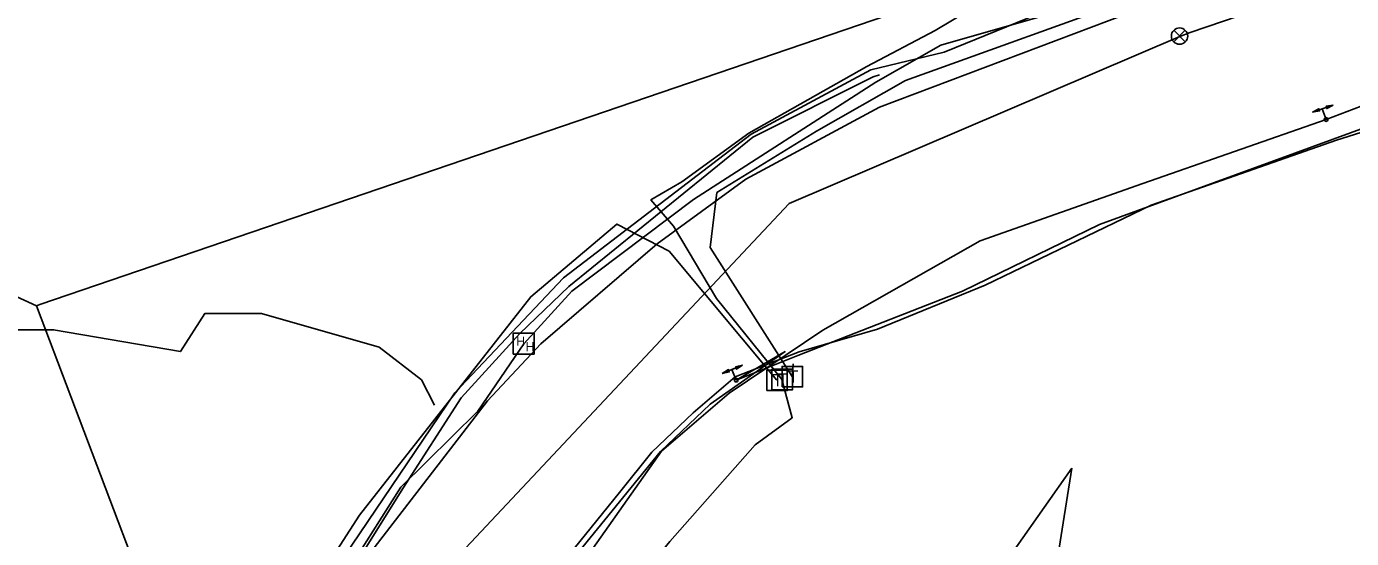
# Model space of a CAD drawing. Extents: x 2070721 to 2083340, y 729290 to 737883.
# Drawn here: x 2080183.4 to 2080544.7, y 734411.8 to 734551.5 of the extents above; entities that cross this region are included whole.
import ezdxf

# ---------------------------------------------------------------- set-up
doc = ezdxf.new("R2010")
doc.units = 0
for name, color, linetype in [('Exist Utilities Other Unknown UG SUE LOS B', 7, 'Continuous'), ('Exist Utilities Power Change of Service SUE CELL', 7, 'Continuous'), ('Exist Utilities Power UG Cable SUE LOS B', 7, 'Continuous'), ('Exist Utilities Power UG Cable SUE LOS C', 7, 'Continuous'), ('Exist Utilities Telephone Hand Hole CELL', 7, 'Continuous'), ('Exist Utilities Telephone Pedestal CELL', 7, 'Continuous'), ('Exist Utilities Telephone UG Cable SUE LOS C', 7, 'Continuous'), ('Exist Utilities Telephone UG Conduit SUE LOS B', 7, 'Continuous'), ('Exist Utilities Telephone UG FO SUE LOS B', 7, 'Continuous'), ('Exist Utilities TV Change of Service SUE CELL', 7, 'Continuous'), ('Exist Utilities TV UG Cable SUE LOS B', 7, 'Continuous'), ('Exist Utilities TV UG FO Cable SUE LOS B', 7, 'Continuous'), ('Exist Utilities TV UG FO Cable SUE LOS C', 7, 'Continuous'), ('Exist Utilities Water UG Line SUE LOS B', 7, 'Continuous'), ('Exist Utilities Water Valve CELL', 7, 'Continuous')]:
    doc.layers.add(name, color=color, linetype=linetype)

msp = doc.modelspace()

# ---------------------------------------------------------------- linework, layer by layer
at = {"layer": 'Exist Utilities Other Unknown UG SUE LOS B'}
msp.add_lwpolyline([(2080237.92, 734293.08), (2080243.61, 734324.09), (2080258.34, 734369.36), (2080269.39, 734398.77), (2080286.02, 734425.45), (2080301.91, 734450.14), (2080317.89, 734467.75), (2080331.23, 734480.5), (2080381.43, 734521.31), (2080414.27, 734537.75), (2080416.02, 734538.24)], dxfattribs=at)
at = {"layer": 'Exist Utilities Power Change of Service SUE CELL'}
for p, q in [((2080539.74, 734530.03), (2080534.11, 734528.06)), ((2080536.78, 734529), (2080539.74, 734530.03)), ((2080537.8, 734526.08), (2080536.78, 734529)), ((2080537.8, 734526.08), (2080537.8, 734526.08))]:
    msp.add_line(p, q, dxfattribs=at)
for points in [[(2080534.11, 734528.06), (2080535.86, 734529.04), (2080535.58, 734528.58), (2080536.04, 734528.41)], [(2080539.74, 734530.03), (2080537.99, 734529.06), (2080538.28, 734529.52), (2080537.82, 734529.68)]]:
    msp.add_lwpolyline(points, close=True, dxfattribs=at)
msp.add_circle((2080537.8, 734526.08), 0.517, dxfattribs=at)
at = {"layer": 'Exist Utilities Power UG Cable SUE LOS B'}
for points in [[(2080374.96, 734451.44), (2080400.56, 734468.64), (2080443.44, 734492.96), (2080487.87, 734508.65), (2080537.8, 734526.08)], [(2080156.43, 734468.74), (2080190.75, 734468.74), (2080225.32, 734462.79), (2080232.03, 734473.2), (2080247.47, 734473.2), (2080279.52, 734463.97), (2080291.1, 734455.07), (2080294.67, 734448.18)], [(2080234.71, 734179.89), (2080280.62, 734187.44), (2080282.92, 734196.34), (2080279.43, 734280.03), (2080304.76, 734362.13), (2080356.55, 734435.67), (2080374.96, 734451.44)], [(2080370.98, 734154.39), (2080361.51, 734212.64), (2080345.43, 734289.41), (2080345.93, 734294.31), (2080384.7, 734326.31), (2080421.96, 734373.11), (2080453.41, 734409.54), (2080468.5, 734430.99)], [(2080468.5, 734430.99), (2080460.53, 734381.1), (2080460.53, 734331.98), (2080467.37, 734277.9), (2080469.6, 734267.89), (2080489.8, 734180.39), (2080505.22, 734135.47), (2080514.45, 734118.41)]]:
    msp.add_lwpolyline(points, dxfattribs=at)
at = {"layer": 'Exist Utilities Power UG Cable SUE LOS C'}
for points in [[(2080186.05, 734475.29), (2080187.03, 734475.63), (2080448.94, 734565.1), (2080663.08, 734641.37), (2080827.26, 734699.95), (2080984.4, 734756.05), (2081109.44, 734801.16), (2081210.88, 734831.9), (2081586.98, 734944.46), (2081830.55, 735019.69), (2082038.54, 735143.44), (2082248.34, 735270.09)], [(2078562.59, 735087.36), (2079031.08, 734900.74), (2079505.61, 734777.36), (2080092.6, 734518.21), (2080186.05, 734475.29)], [(2080537.8, 734526.08), (2080558.84, 734534.05), (2080639.7, 734564.08), (2080660.56, 734567.92), (2080667.78, 734563.47)], [(2080186.05, 734475.29), (2080232.86, 734351.65), (2080379.47, 733942.04), (2080251.03, 733903.89)]]:
    msp.add_lwpolyline(points, dxfattribs=at)
at = {"layer": 'Exist Utilities Telephone Hand Hole CELL'}
for p, q in [((2080316.13, 734467.81), (2080316.13, 734462.09)), ((2080321.85, 734467.81), (2080316.13, 734467.81)), ((2080321.85, 734462.09), (2080321.85, 734467.81)), ((2080318.99, 734464.95), (2080318.99, 734464.95)), ((2080316.13, 734462.09), (2080321.85, 734462.09))]:
    msp.add_line(p, q, dxfattribs=at)
at = {"layer": 'Exist Utilities Telephone Pedestal CELL'}
for p, q in [((2080387.98, 734454.99), (2080387.98, 734454.99)), ((2080389.38, 734455.18), (2080389.38, 734455.18)), ((2080392.18, 734455.98), (2080392.18, 734455.98))]:
    msp.add_line(p, q, dxfattribs=at)
for points in [[(2080385.26, 734452.16), (2080390.85, 734452.16), (2080390.85, 734457.76), (2080385.26, 734457.76), (2080385.26, 734452.16)], [(2080386.66, 734452.35), (2080392.25, 734452.35), (2080392.25, 734457.95), (2080386.66, 734457.95), (2080386.66, 734452.35)], [(2080389.46, 734453.15), (2080395.05, 734453.15), (2080395.05, 734458.75), (2080389.46, 734458.75), (2080389.46, 734453.15)]]:
    msp.add_lwpolyline(points, dxfattribs=at)
at = {"layer": 'Exist Utilities Telephone UG Cable SUE LOS C'}
for points in [[(2080392.43, 734459.45), (2080392.18, 734455.98), (2080369.79, 734491.21), (2080371.64, 734506.16), (2080398.8, 734522.93), (2080423.1, 734536.76), (2080488.87, 734560.43), (2080551.19, 734581.93), (2080605.97, 734600.8), (2080683.17, 734629.37), (2080713.38, 734633.09), (2080745.42, 734609.78), (2080760.77, 734576.63), (2080781.91, 734561.06), (2080789.84, 734547.84), (2080795.45, 734523.96), (2080798.47, 734502.81), (2080795.45, 734476.11), (2080787.39, 734456.13)], [(2080389.44, 734455.05), (2080371.58, 734477.3), (2080359.8, 734497.02), (2080353.64, 734504.17), (2080362.14, 734509.13), (2080380.41, 734522.38), (2080412.54, 734540.56), (2080431.18, 734550.33), (2080456.15, 734565.37), (2080500.74, 734587.65), (2080527.18, 734594.58)], [(2080179.48, 734239.75), (2080182.79, 734239.75), (2080204.44, 734237.74), (2080223.27, 734244.14), (2080227.06, 734249.97), (2080225.75, 734270.22), (2080228.23, 734298.53), (2080237.75, 734333.83), (2080246.14, 734355.32), (2080258.39, 734393.6), (2080274.22, 734418.19), (2080320.87, 734477.75), (2080344.36, 734497.56), (2080358.62, 734490.18), (2080387.98, 734454.99)], [(2080294.22, 734238.68), (2080294.22, 734255.9), (2080294.22, 734291.26), (2080298.27, 734306.08), (2080307.66, 734333.57), (2080322.1, 734363.11), (2080329.68, 734375.34), (2080358.78, 734411), (2080382.14, 734437.37), (2080392.23, 734444.72), (2080389.38, 734455.18)]]:
    msp.add_lwpolyline(points, dxfattribs=at)
at = {"layer": 'Exist Utilities Telephone UG Conduit SUE LOS B'}
msp.add_lwpolyline([(2080232.24, 734245.67), (2080237.5, 734254.36), (2080238.66, 734282.35), (2080245.75, 734323.83), (2080258.86, 734369.55), (2080269.86, 734398.57), (2080309.08, 734449.32), (2080323.63, 734464.88), (2080355.41, 734492.16), (2080379.52, 734509.8), (2080416.03, 734529.49), (2080502.71, 734562.3), (2080573.96, 734587.12), (2080616.57, 734603.22), (2080677.16, 734624.99), (2080749, 734651.22), (2080815.57, 734674.3), (2080861.11, 734690.56), (2080923.26, 734714.15), (2080934.26, 734720.97)], dxfattribs=at)
at = {"layer": 'Exist Utilities Telephone UG FO SUE LOS B'}
for points in [[(2080235.11, 734249.36), (2080234.94, 734252.48), (2080236.58, 734281.87), (2080244.62, 734323.58), (2080257.8, 734369.84), (2080268.59, 734399.28), (2080285.42, 734425.78), (2080306.49, 734446.52), (2080318.99, 734464.89), (2080332.07, 734479.26), (2080365.28, 734504.24), (2080415, 734536.31), (2080432.75, 734546.34), (2080471.85, 734557.5), (2080502.31, 734568.65), (2080534.18, 734580.2), (2080570.94, 734591.77), (2080576.66, 734593.81), (2080717.24, 734648.01)], [(2080228.28, 734243.43), (2080230.55, 734282.39), (2080237.1, 734324.84), (2080265.61, 734400.42), (2080300.19, 734451.55), (2080329.83, 734482.91), (2080380.99, 734522.11), (2080413.6, 734539.64), (2080433.63, 734544.47), (2080470.56, 734559.5), (2080533.58, 734581.77), (2080652.68, 734625.4)]]:
    msp.add_lwpolyline(points, dxfattribs=at)
at = {"layer": 'Exist Utilities TV Change of Service SUE CELL'}
for p, q in [((2080378.66, 734459.04), (2080373.12, 734456.82)), ((2080375.75, 734457.87), (2080378.66, 734459.04)), ((2080376.9, 734455.01), (2080375.75, 734457.87)), ((2080376.9, 734455.01), (2080376.9, 734455.01))]:
    msp.add_line(p, q, dxfattribs=at)
for points in [[(2080373.12, 734456.82), (2080374.83, 734457.87), (2080374.56, 734457.4), (2080375.03, 734457.26)], [(2080378.66, 734459.04), (2080376.96, 734457.99), (2080377.22, 734458.46), (2080376.75, 734458.61)]]:
    msp.add_lwpolyline(points, close=True, dxfattribs=at)
msp.add_circle((2080376.9, 734455.01), 0.517, dxfattribs=at)
at = {"layer": 'Exist Utilities TV UG Cable SUE LOS B'}
msp.add_lwpolyline([(2080278.08, 734231.48), (2080277, 734239.67), (2080277, 734275.25), (2080279.3, 734284.9), (2080288.08, 734317.87), (2080293.24, 734335.92), (2080296.25, 734346.26), (2080298.88, 734355.59), (2080304.96, 734366.83), (2080310.77, 734377.58), (2080320.31, 734392.98), (2080332.74, 734409.06), (2080345.11, 734424.32), (2080353.93, 734435.35), (2080365.15, 734446.1), (2080376.65, 734455.86), (2080394.1, 734462.75), (2080415.44, 734468.86), (2080444.8, 734480.86), (2080490.14, 734502.72), (2080540.63, 734520.42), (2080564.59, 734528.02)], dxfattribs=at)
at = {"layer": 'Exist Utilities TV UG FO Cable SUE LOS B'}
msp.add_lwpolyline([(2080232.67, 734236.44), (2080273.72, 734233.3), (2080278.08, 734231.48), (2080279.38, 734279.77), (2080300.6, 734357.07), (2080319.92, 734390.91), (2080356.3, 734435.5), (2080369.79, 734448.44), (2080390.27, 734462.8), (2080376.9, 734455.01)], dxfattribs=at)
at = {"layer": 'Exist Utilities TV UG FO Cable SUE LOS C'}
msp.add_lwpolyline([(2080376.9, 734455.01), (2080393.72, 734461.75), (2080438.63, 734479.28), (2080476.05, 734497.46), (2080571.1, 734532.14), (2080615.4, 734550.71)], dxfattribs=at)
at = {"layer": 'Exist Utilities Water UG Line SUE LOS B'}
msp.add_lwpolyline([(2080357.06, 734003.27), (2080353.32, 734006.79), (2080296.63, 734072.2), (2080261.95, 734141.13), (2080251.22, 734185.42), (2080250, 734189.2), (2080244.12, 734248.6), (2080244.13, 734251.5), (2080244.63, 734259.68), (2080245.13, 734264.1), (2080254.44, 734320.44), (2080276.53, 734380.91), (2080391.41, 734503.18), (2080497.9, 734548.7), (2080500.72, 734549.83), (2080585.45, 734578.7), (2080702.53, 734619.89), (2080710.17, 734622.62), (2080743.51, 734634.52), (2080754.26, 734638.28), (2080902.52, 734692.58), (2081024.44, 734735.33)], dxfattribs=at)
at = {"layer": 'Exist Utilities Water Valve CELL'}
msp.add_lwpolyline([(2080499.42, 734550.41), (2080496.27, 734547.26), (2080497.84, 734548.83), (2080499.42, 734547.26), (2080496.27, 734550.41)], dxfattribs=at)
msp.add_circle((2080497.84, 734548.83), 2.23, dxfattribs=at)

# ---------------------------------------------------------------- texts
at = {"layer": 'Exist Utilities Telephone Hand Hole CELL'}
for p in [(2080316.91, 734464.36), (2080319.48, 734462.89)]:
    msp.add_text('H', height=2.5, dxfattribs=at).set_placement(p)
at = {"layer": 'Exist Utilities Telephone Pedestal CELL'}
for p in [(2080386.85, 734453.28), (2080388.25, 734453.47), (2080391.05, 734454.27)]:
    msp.add_text('T', height=3.42, dxfattribs=at).set_placement(p)

doc.saveas('drawing.dxf')
